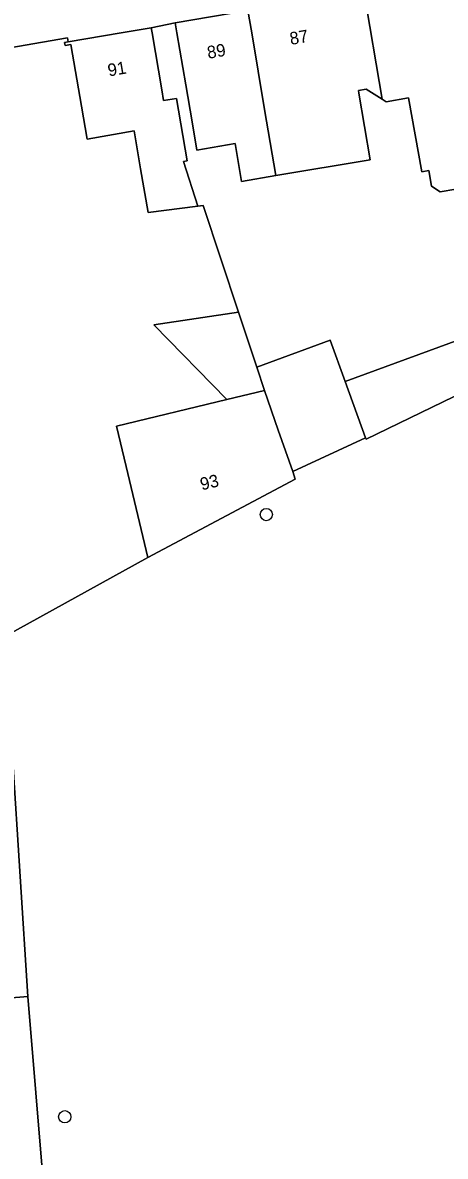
# Model space of a CAD drawing. Extents: x 162879 to 165540, y 384011 to 385181.
# Drawn here: x 164187.3 to 164221.1, y 384410.1 to 384500.8 of the extents above; entities that cross this region are included whole.
import ezdxf

# ---------------------------------------------------------------- set-up
doc = ezdxf.new("R2010")
doc.units = 0
for name, color, linetype in [('IMGEO_Boom', 7, 'Continuous'), ('IMGEO_Erf', 7, 'Continuous'), ('IMGEO_Groenvoorziening', 7, 'Continuous'), ('IMGEO_Pand', 7, 'Continuous'), ('IMGEO_Pand_nummerreeks', 7, 'Continuous'), ('IMGEO_Voetpad_open', 7, 'Continuous')]:
    doc.layers.add(name, color=color, linetype=linetype)

msp = doc.modelspace()

# ---------------------------------------------------------------- linework, layer by layer
at = {"layer": 'IMGEO_Boom'}
for centre in [(164206.796, 384461.451), (164190.654, 384413.259)]:
    msp.add_circle(centre, 0.489, dxfattribs=at)
at = {"layer": 'IMGEO_Erf'}
for points in [[(164221.97, 384487.5), (164220.732, 384487.286), (164220.019, 384487.739), (164219.798, 384488.989), (164219.239, 384488.89), (164218.191, 384494.795), (164216.406, 384494.487), (164216.064, 384494.701), (164214.799, 384495.491), (164214.178, 384495.386), (164214.213, 384495.18), (164215.114, 384489.851), (164207.554, 384488.573), (164204.821, 384488.103), (164204.297, 384491.149), (164201.243, 384490.625), (164200.857, 384492.872), (164200.347, 384495.838), (164199.633, 384500), (164199.496, 384500.802), (164197.576, 384500.409), (164197.645, 384500), (164198.416, 384495.435), (164198.565, 384494.574), (164199.597, 384494.752), (164200.459, 384489.766), (164200.169, 384489.716), (164201.318, 384486.14), (164201.741, 384486.196), (164204.579, 384477.644), (164206.037, 384473.251), (164211.908, 384475.4), (164213.112, 384472.11), (164223.804, 384476.024)], [(164181.159, 384422.347), (164187.698, 384422.888), (164185.85, 384451.698), (164197.318, 384458.015), (164195.575, 384465.304), (164194.806, 384468.521), (164203.64, 384470.652), (164197.778, 384476.636), (164204.579, 384477.644), (164201.741, 384486.196), (164201.318, 384486.14), (164197.337, 384485.617), (164196.731, 384489.121), (164196.208, 384492.148), (164192.444, 384491.497), (164191.988, 384494.135), (164191.137, 384499.061), (164190.686, 384498.983), (164190.643, 384499.232), (164190.914, 384499.278), (164190.862, 384499.594), (164170.209, 384496.04)]]:
    msp.add_lwpolyline(points, dxfattribs=at)
at = {"layer": 'IMGEO_Groenvoorziening'}
msp.add_lwpolyline([(164245.298, 384436.718), (164244.478, 384442.106), (164242.874, 384441.867), (164239.697, 384463.469), (164239.692, 384464.099), (164228.143, 384458.963), (164224.178, 384467.878), (164222.661, 384471.289), (164214.783, 384467.494), (164214.752, 384467.581), (164208.911, 384464.892), (164209.118, 384464.295), (164197.318, 384458.015), (164185.85, 384451.698), (164187.698, 384422.888), (164189.639, 384399.425), (164189.648, 384399.321), (164208.009, 384396.555), (164215.994, 384398.385), (164222.545, 384404.326), (164225.506, 384407.797), (164233.312, 384416.027), (164242.862, 384429.386), (164246.31, 384430.071)], close=True, dxfattribs=at)
at = {"layer": 'IMGEO_Pand'}
for points in [[(164223.68, 384499.044), (164223.511, 384500), (164222.661, 384504.819), (164222.656, 384504.846), (164216.306, 384503.726), (164216.321, 384503.641), (164214.6, 384503.351), (164216.064, 384494.701), (164216.406, 384494.487), (164218.191, 384494.795), (164219.239, 384488.89), (164219.798, 384488.989), (164220.019, 384487.739), (164220.732, 384487.286), (164221.97, 384487.5), (164222.402, 384488.102), (164222.179, 384489.367), (164223.327, 384489.57), (164223.508, 384488.547), (164225.405, 384488.883), (164225.219, 384489.933), (164225.98, 384490.067), (164225.669, 384491.824), (164224.981, 384491.702)], [(164214.6, 384503.351), (164212.881, 384503.061), (164205.325, 384501.786), (164205.625, 384500), (164206.659, 384493.875), (164207.554, 384488.573), (164215.114, 384489.851), (164214.213, 384495.18), (164214.178, 384495.386), (164214.799, 384495.491), (164216.064, 384494.701)], [(164205.325, 384501.786), (164199.496, 384500.802), (164199.633, 384500), (164200.347, 384495.838), (164200.857, 384492.872), (164201.243, 384490.625), (164204.297, 384491.149), (164204.821, 384488.103), (164207.554, 384488.573), (164206.659, 384493.875), (164205.625, 384500)], [(164198.416, 384495.435), (164197.645, 384500), (164197.576, 384500.409), (164195.167, 384500), (164190.914, 384499.278), (164190.643, 384499.232), (164190.686, 384498.983), (164191.137, 384499.061), (164191.988, 384494.135), (164192.444, 384491.497), (164196.208, 384492.148), (164196.731, 384489.121), (164197.337, 384485.617), (164201.318, 384486.14), (164200.169, 384489.716), (164200.459, 384489.766), (164199.597, 384494.752), (164198.565, 384494.574)], [(164204.579, 384477.644), (164197.778, 384476.636), (164203.64, 384470.652), (164206.658, 384471.38), (164206.037, 384473.251)], [(164213.112, 384472.11), (164211.908, 384475.4), (164206.037, 384473.251), (164206.658, 384471.38), (164207.756, 384468.217), (164208.911, 384464.892), (164214.752, 384467.581)], [(164225.139, 384472.483), (164223.804, 384476.024), (164213.112, 384472.11), (164214.752, 384467.581), (164214.783, 384467.494), (164222.661, 384471.289)], [(164209.118, 384464.295), (164208.911, 384464.892), (164207.756, 384468.217), (164206.658, 384471.38), (164203.64, 384470.652), (164194.806, 384468.521), (164195.575, 384465.304), (164197.318, 384458.015)], [(164189.648, 384399.321), (164189.639, 384399.425), (164187.698, 384422.888), (164181.159, 384422.347), (164181.926, 384413.075), (164181.409, 384413.032), (164181.56, 384411.207), (164167.263, 384413.457), (164165.633, 384403.1), (164171.175, 384402.228)]]:
    msp.add_lwpolyline(points, close=True, dxfattribs=at)
at = {"layer": 'IMGEO_Voetpad_open'}
msp.add_lwpolyline([(164170.209, 384496.04), (164190.862, 384499.594), (164190.914, 384499.278), (164195.167, 384500), (164197.576, 384500.409), (164199.496, 384500.802), (164205.325, 384501.786)], dxfattribs=at)

# ---------------------------------------------------------------- texts
at = {"layer": 'IMGEO_Pand_nummerreeks'}
for s, rotation, p in [('87', 9.55694, (164208.753, 384499.033)), ('89', 9.57959, (164202.141, 384497.922)), ('91', 9.63715, (164194.181, 384496.507)), ('93', 13.44732, (164201.628, 384463.379))]:
    msp.add_text(s, height=1, rotation=rotation, dxfattribs=at).set_placement(p)

doc.saveas('drawing.dxf')
